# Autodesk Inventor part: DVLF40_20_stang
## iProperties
Created: 2009-11
Part Number: DVLF40_20_stang
Document SubType Name: Modeling
Designer: TB
Mass: 89.9528 g
Surface Area: 173.108 cm^2
Volume: 89.9528 cm^3
Density: 1 g/cm^3
Author: TB
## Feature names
1. Revolution1
2. Fillet1
3. Revolution2
